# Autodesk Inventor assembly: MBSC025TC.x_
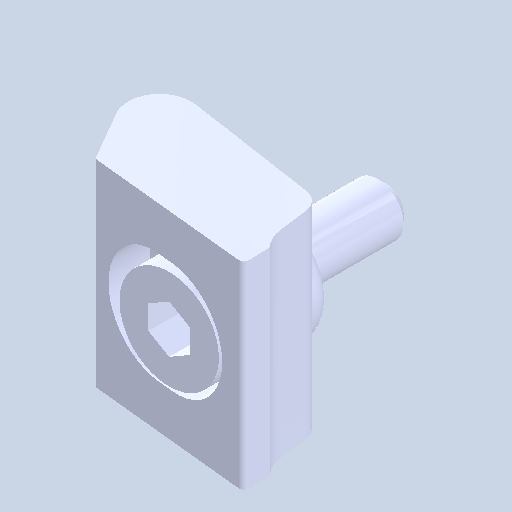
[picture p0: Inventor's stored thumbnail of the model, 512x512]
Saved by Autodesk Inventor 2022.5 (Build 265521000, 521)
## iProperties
Created: 2024-05
Part Number: MBSC025TC.x_
Document SubType Name: Assembly
Designer: ImaoCorp
Author: ImaoCorp
Sending System: SOLIDWORKS 2022-2022290
MC: AMD64
MC_MODEL: Intel64 Family 6 Model 60 Stepping 3, GenuineIntel
OS: Windows_NT
FRU: Parasolid Version 33.1, build 260,  4-25-2022
FORMAT: text
GUISE: transmit
KEY: FILEMBSC025TC.x_t
DATE: Mon May 20 16:27:58 2024
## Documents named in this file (4)
- X:\14_SW2022-Inv2022\保留中\mitee-bite\データ\mbsc025tc\MBSC025TC.x_.iam
- X:\14_SW2022-Inv2022\保留中\mitee-bite\データ\mbsc025tc\MBSC025TC_01.ipt
- X:\14_SW2022-Inv2022\保留中\mitee-bite\データ\mbsc025tc\MBSC025TC_02.ipt
- X:\14_SW2022-Inv2022\保留中\mitee-bite\データ\mbsc025tc\MBSC025TC_03.ipt
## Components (3 placed, 3 different names)
1. MBSC025TC_01
2. MBSC025TC_02
3. MBSC025TC_03
